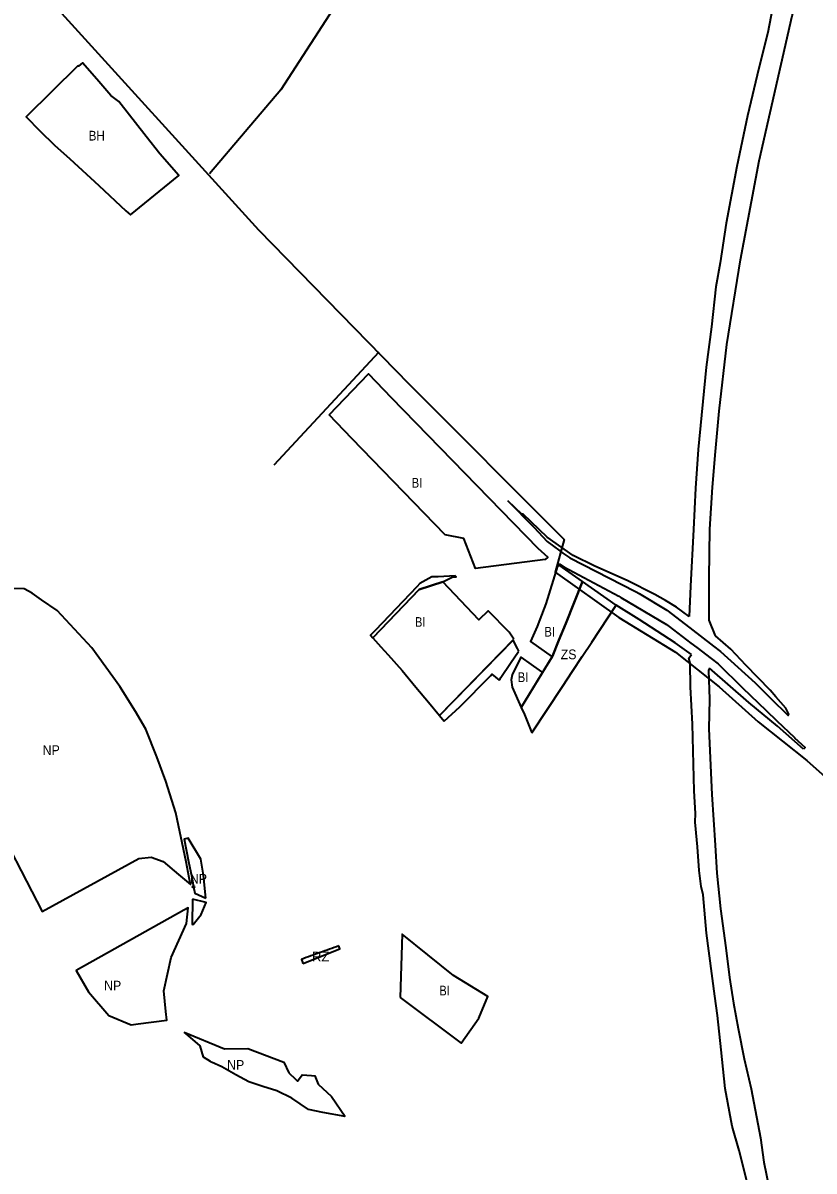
# Model space of a CAD drawing. Extents: x -650276 to -642489, y -1074311 to -1066658.
# Drawn here: x -646196 to -645218, y -1073124 to -1071706 of the extents above; entities that cross this region are included whole.
import ezdxf

# ---------------------------------------------------------------- set-up
doc = ezdxf.new("R2010")
doc.units = 0
doc.header["$LTSCALE"] = 4.8
doc.header["$PDMODE"] = 32
doc.header["$PDSIZE"] = 2.4
for name, color, linetype, lineweight in [('1', 7, 'Continuous', 35), ('15', 7, 'Continuous', 35), ('2', 7, 'Continuous', 35), ('24', 7, 'Continuous', 35), ('41', 7, 'Continuous', 35), ('48', 7, 'Continuous', 35), ('54', 7, 'Continuous', 35), ('6', 7, 'Continuous', 35)]:
    doc.layers.add(name, color=color, linetype=linetype, lineweight=lineweight)
doc.layers.add('62', color=7, linetype='Continuous')

msp = doc.modelspace()

# ---------------------------------------------------------------- linework, layer by layer
at = {"layer": '1'}
msp.add_lwpolyline([(-646102.04, -1071906.4), (-646068.317, -1071937.555), (-646062.91, -1071942.55), (-646002.93, -1071893.984), (-646026.64, -1071867.44), (-646043.49, -1071845.87), (-646077.32, -1071802.59), (-646087, -1071795), (-646104.5, -1071774.86), (-646122.16, -1071754.78), (-646127.12, -1071759.15), (-646127.84, -1071758.53), (-646191.57, -1071821.44), (-646174.69, -1071838.69), (-646156.59, -1071856.53), (-646137.74, -1071873.31)], close=True, dxfattribs=at)
at = {"layer": '15'}
for points in [[(-645661.3, -1072388.74), (-645682.59, -1072389.76), (-645690.37, -1072390.13), (-645705, -1072398.19), (-645708.94, -1072402.11)], [(-645676.53, -1072396.16), (-645676.53, -1072396.16), (-645665.32, -1072390.32), (-645660.16, -1072389.95), (-645661.3, -1072388.74)], [(-645708.94, -1072402.11), (-645760.02, -1072455.94), (-645765.95, -1072462.03), (-645763.06, -1072465.26)], [(-645763.06, -1072465.26), (-645706.039, -1072405.769), (-645676.53, -1072396.16)], [(-645582.84, -1072481.71), (-645584.46, -1072478.58), (-645589.862, -1072468.109), (-645680.87, -1072561.42), (-645675.13, -1072568.36)], [(-645607.07, -1072517.61), (-645605.95, -1072515.95), (-645604.82, -1072514.3), (-645592.9, -1072496.52), (-645583.13, -1072482.13), (-645582.84, -1072481.71)], [(-645675.13, -1072568.36), (-645655.65, -1072550.62), (-645617.87, -1072512.12), (-645615.95, -1072510.16), (-645607.07, -1072517.61)]]:
    msp.add_lwpolyline(points, dxfattribs=at)
at = {"layer": '2'}
for points in [[(-645817.219, -1072189.975), (-645768.649, -1072139.283), (-645740.45, -1072168.23), (-645559.34, -1072354.42), (-645546.82, -1072365.72), (-645550.41, -1072368.47), (-645636.37, -1072379.57), (-645650.78, -1072342.73), (-645674, -1072338), (-645789.298, -1072218.833)], [(-645503.98, -1072395.64), (-645532.75, -1072375.41), (-645535.05, -1072376.72), (-645549.6, -1072423.39), (-645551.54, -1072428.66), (-645559.92, -1072451.41), (-645568.38, -1072469.68), (-645541.56, -1072488.74), (-645553.35, -1072508.1), (-645554.477, -1072507.299), (-645579.92, -1072489.22), (-645581.13, -1072491), (-645591.06, -1072511.06), (-645592.08, -1072517.43), (-645591.03, -1072526.14), (-645579.76, -1072551.45), (-645541.09, -1072487.98), (-645533.15, -1072468.21), (-645524.87, -1072447.61)], [(-645588.78, -1072467), (-645594.83, -1072458.48), (-645620.56, -1072432), (-645632.1, -1072442.93), (-645676.53, -1072396.16), (-645706.039, -1072405.769), (-645763.06, -1072465.26), (-645753.128, -1072476.383), (-645744.38, -1072486.18), (-645726.95, -1072505.7), (-645709.92, -1072526.3), (-645694.51, -1072544.93), (-645680.87, -1072561.42)], [(-645729.36, -1072909.65), (-645654.16, -1072966.3), (-645632.23, -1072935.28), (-645620.92, -1072908.65), (-645663.52, -1072882.58), (-645726.9, -1072831.5)]]:
    msp.add_lwpolyline(points, close=True, dxfattribs=at)
at = {"layer": '24'}
for points in [[(-645339.904, -1072462.677), (-645347.551, -1072443.527), (-645347.677, -1072391.355), (-645346.62, -1072330.914), (-645343.458, -1072278.998), (-645339.908, -1072235.158), (-645335.367, -1072185.207), (-645325.498, -1072102.789), (-645309.01, -1071998.147), (-645285.617, -1071875.733), (-645244.798, -1071696.585), (-645235.793, -1071663.703), (-645230.436, -1071634.261), (-645227.905, -1071625.277), (-645222.48, -1071606.08)], [(-645339.904, -1072462.677), (-645347.551, -1072443.527), (-645347.677, -1072391.355), (-645346.62, -1072330.914), (-645343.458, -1072278.998), (-645339.908, -1072235.158), (-645335.367, -1072185.207), (-645325.498, -1072102.789), (-645309.01, -1071998.147), (-645285.617, -1071875.733), (-645244.798, -1071696.585), (-645235.793, -1071663.703), (-645230.436, -1071634.261), (-645227.905, -1071625.277), (-645222.48, -1071606.08)], [(-645255.662, -1071626.67), (-645261.094, -1071645.025), (-645264.841, -1071657.687), (-645269.077, -1071687.396), (-645274.868, -1071717.176), (-645286.175, -1071761.228), (-645300.076, -1071820.179), (-645313.153, -1071883.081), (-645326.343, -1071952.807)], [(-645255.662, -1071626.67), (-645261.094, -1071645.025), (-645264.841, -1071657.687), (-645269.077, -1071687.396), (-645274.868, -1071717.176), (-645286.175, -1071761.228), (-645300.076, -1071820.179), (-645313.153, -1071883.081)], [(-645313.153, -1071883.081), (-645326.343, -1071952.807), (-645334.118, -1072001.954), (-645339.455, -1072031.565), (-645344.819, -1072081.225), (-645351.358, -1072130.815), (-645361.317, -1072232.824), (-645364.435, -1072280.268), (-645366.951, -1072331.609), (-645370.624, -1072401.447), (-645372.228, -1072438.764)], [(-645326.343, -1071952.807), (-645334.118, -1072001.954), (-645339.455, -1072031.565), (-645344.819, -1072081.225), (-645351.358, -1072130.815), (-645361.317, -1072232.824), (-645364.435, -1072280.268), (-645366.951, -1072331.609), (-645370.624, -1072401.447), (-645372.228, -1072438.764)], [(-645372.228, -1072438.764), (-645387.894, -1072427.453), (-645401.441, -1072419.033), (-645414.631, -1072411.611), (-645448.831, -1072394.325), (-645488.64, -1072376.782), (-645515.437, -1072363.447), (-645547.593, -1072340.827), (-645577.33, -1072312.704), (-645579.217, -1072312.425), (-645596.405, -1072296.114)], [(-645596.405, -1072296.114), (-645564.4, -1072328.61), (-645547.72, -1072346.19), (-645532.07, -1072358.01), (-645531.65, -1072358.29), (-645528.27, -1072360.53), (-645519.57, -1072366.3), (-645438.64, -1072408.1)], [(-645372.228, -1072438.764), (-645387.894, -1072427.453), (-645401.441, -1072419.033), (-645414.631, -1072411.611), (-645448.831, -1072394.325), (-645488.64, -1072376.782), (-645515.437, -1072363.447), (-645547.593, -1072340.827), (-645577.33, -1072312.704), (-645579.217, -1072312.425), (-645596.405, -1072296.114)], [(-645596.405, -1072296.114), (-645564.4, -1072328.61), (-645547.72, -1072346.19), (-645532.07, -1072358.01), (-645531.65, -1072358.29), (-645528.27, -1072360.53), (-645519.57, -1072366.3), (-645438.64, -1072408.1)], [(-645462.646, -1072425.015), (-645503.98, -1072395.64), (-645532.75, -1072375.41), (-645534.3, -1072374.33), (-645533.08, -1072373.71)], [(-645533.08, -1072373.71), (-645527.33, -1072377.73), (-645459.31, -1072413.95), (-645456.52, -1072415.6), (-645400.12, -1072449.03), (-645396.94, -1072451.44), (-645370.226, -1072471.736)], [(-645438.64, -1072408.1), (-645437.6, -1072408.64), (-645434.19, -1072410.67), (-645399.77, -1072431.12), (-645371.356, -1072453.119), (-645342.284, -1072475.625)], [(-645438.64, -1072408.1), (-645437.6, -1072408.64), (-645434.19, -1072410.67), (-645399.77, -1072431.12), (-645371.356, -1072453.119), (-645342.284, -1072475.625), (-645333.62, -1072482.33), (-645290.76, -1072520.92)], [(-645369.364, -1072485.931), (-645389.731, -1072471.612), (-645404.64, -1072461.72), (-645433.91, -1072442.56), (-645462.646, -1072425.015)], [(-645370.226, -1072471.736), (-645362.81, -1072477.37), (-645345.079, -1072490.836)], [(-645290.76, -1072520.92), (-645271.74, -1072539.96), (-645249.9, -1072561.25), (-645248.967, -1072559.511), (-645252.768, -1072552.178), (-645265.009, -1072538.358), (-645272.276, -1072530.154), (-645302.303, -1072499.014), (-645320.805, -1072479.495), (-645339.904, -1072462.677)], [(-645290.76, -1072520.92), (-645271.74, -1072539.96), (-645249.9, -1072561.25), (-645248.967, -1072559.511), (-645252.768, -1072552.178), (-645265.009, -1072538.358), (-645272.276, -1072530.154), (-645302.303, -1072499.014), (-645320.805, -1072479.495), (-645339.904, -1072462.677)], [(-645364.524, -1072682.575), (-645366.022, -1072654.462), (-645368.173, -1072571.881), (-645370.755, -1072525.734), (-645370.928, -1072496.619), (-645372.72, -1072490.314), (-645369.364, -1072485.931)], [(-645342.284, -1072475.625), (-645333.62, -1072482.33), (-645290.76, -1072520.92)], [(-645347.292, -1072502.877), (-645348.253, -1072505.583), (-645347.214, -1072540.97), (-645347.795, -1072577.893), (-645344.152, -1072658.857), (-645339.96, -1072721.587), (-645338.023, -1072755.969), (-645333.718, -1072799.987)], [(-645230.845, -1072602.888), (-645263.217, -1072574.314), (-645298.498, -1072545.352), (-645347.292, -1072502.877)], [(-645345.079, -1072490.836), (-645336.33, -1072497.48), (-645306.46, -1072527.08), (-645276.93, -1072555.11), (-645263.7, -1072567.8), (-645242, -1072588.6), (-645241.87, -1072588.722), (-645228.96, -1072600.865), (-645230.845, -1072602.888)], [(-645357.272, -1072772.771), (-645359.76, -1072752.865), (-645361.874, -1072723.527), (-645362.708, -1072714.781), (-645364.786, -1072692.977), (-645364.524, -1072682.575)], [(-645271.518, -1073261.16), (-645272.747, -1073256.762), (-645275.269, -1073240.71), (-645276.125, -1073226.571), (-645288.647, -1073184.518), (-645297.395, -1073151.294), (-645310.558, -1073098.946), (-645319.052, -1073068.6), (-645327.554, -1073022.214), (-645332.517, -1072974.538), (-645337.34, -1072932.073), (-645340.345, -1072908.029), (-645350.822, -1072830.388), (-645354.019, -1072792.454), (-645355.121, -1072782.993), (-645357.272, -1072772.771)], [(-645333.718, -1072799.987), (-645327.091, -1072848.387), (-645322.284, -1072885.085), (-645317.65, -1072916.642)], [(-645317.65, -1072916.642), (-645311.772, -1072947.945), (-645304.24, -1072985.372), (-645295.788, -1073022.556)], [(-645295.788, -1073022.556), (-645284.269, -1073083.286), (-645279.878, -1073113.356), (-645262.388, -1073199.409), (-645257.842, -1073221.36), (-645247.051, -1073248.736), (-645239.9, -1073270.025), (-645226.847, -1073278.345), (-645227.199, -1073283.366), (-645227.744, -1073292.736)]]:
    msp.add_lwpolyline(points, dxfattribs=at)
at = {"layer": '41'}
msp.add_line((-645566.54, -1072582.88), (-645528.81, -1072525.54), dxfattribs=at)
msp.add_lwpolyline([(-645528.81, -1072525.54), (-645516.37, -1072506.64), (-645504.48, -1072488.58), (-645492.61, -1072470.54), (-645462.65, -1072425.01), (-645503.98, -1072395.64), (-645524.87, -1072447.61), (-645533.15, -1072468.21), (-645541.09, -1072487.98), (-645553.35, -1072508.1), (-645579.76, -1072551.45), (-645575.9, -1072560.13), (-645566.54, -1072582.88)], dxfattribs=at)
at = {"layer": '48'}
for points in [[(-646236.97, -1072678.31), (-646171.72, -1072803.51), (-646052.58, -1072737.82), (-646037.23, -1072736.38), (-646022.4, -1072741.58), (-646003.22, -1072757.85), (-645988.43, -1072769.93), (-645990.04, -1072761.78), (-645993.89, -1072742.23), (-646006.66, -1072681.4), (-646019.16, -1072642.35), (-646030.17, -1072612.31), (-646043.87, -1072578.12), (-646056.42, -1072556.49), (-646075.82, -1072525.54), (-646110.61, -1072477.49), (-646153.49, -1072431.54), (-646172.81, -1072418.2), (-646184.449, -1072410.256), (-646194.19, -1072404.62), (-646254.75, -1072404.25)], [(-645969.46, -1072787.03), (-645972.31, -1072758.48), (-645975.86, -1072738.61), (-645991.31, -1072712.86), (-645996.31, -1072714.11), (-645990.95, -1072741.65), (-645987.1, -1072761.2), (-645984.79, -1072772.91)], [(-645984.79, -1072772.91), (-645983.22, -1072780.88), (-645969.46, -1072787.03)], [(-645986.24, -1072788.33), (-645986.71, -1072819.26), (-645986.71, -1072819.26)], [(-645975.3, -1072807.37), (-645969.01, -1072792.28), (-645986.24, -1072788.33)], [(-645986.71, -1072819.26), (-645986.71, -1072819.26), (-645985.19, -1072819.72), (-645975.3, -1072807.37)], [(-645972.6, -1072983.41), (-645976.48, -1072969.55), (-645988.49, -1072959.28), (-645996.2, -1072952.69)], [(-645996.2, -1072952.69), (-645946.4, -1072973.05), (-645917.53, -1072972.93), (-645873.3, -1072989.79), (-645866.93, -1073002.72)], [(-645863.39, -1073034.25), (-645882.07, -1073025.22), (-645899.35, -1073019.65), (-645916.47, -1073014.03), (-645932.44, -1073005.5), (-645949.85, -1072995.57), (-645962.81, -1072989.45), (-645963.77, -1072989), (-645972.6, -1072983.41)], [(-645866.93, -1073002.72), (-645858.82, -1073010.74), (-645856.46, -1073013.07), (-645850.37, -1073005.42), (-645838.89, -1073006.18)], [(-645838.89, -1073006.18), (-645834.9, -1073006.45), (-645830.6, -1073016.92), (-645814.27, -1073032.11), (-645797.32, -1073056.62)], [(-645797.32, -1073056.62), (-645824.93, -1073051.83), (-645842.53, -1073048.19), (-645863.39, -1073034.25)]]:
    msp.add_lwpolyline(points, dxfattribs=at)
msp.add_lwpolyline([(-645993.47, -1072818.44), (-645991.37, -1072798.84), (-645996.8, -1072801.88), (-646129.91, -1072876.24), (-646114.5, -1072902.8), (-646089.39, -1072931.92), (-646062.04, -1072943.58), (-646053.287, -1072942.399), (-646017.65, -1072937.59), (-646019.21, -1072926.91), (-646021.64, -1072901.6), (-646012.37, -1072860.3)], close=True, dxfattribs=at)
msp.add_point((-645984.79, -1072772.91), dxfattribs=at)
at = {"layer": '54'}
msp.add_line((-645885.363, -1072251.506), (-645755.385, -1072111.972), dxfattribs=at)
for points in [[(-645648.577, -1071395.44), (-645803.784, -1071674.386), (-645877, -1071788), (-645965, -1071892)], [(-646336.784, -1071524.232), (-646218.737, -1071612.767), (-646164.374, -1071674.897), (-645904.456, -1071961.331), (-645718.199, -1072151.712), (-645526.944, -1072343.922), (-645538, -1072384), (-645459, -1072440), (-645389, -1072483), (-645335, -1072526), (-645287, -1072569), (-645227, -1072617), (-645139.573, -1072694.628), (-645084.365, -1072788.086)]]:
    msp.add_lwpolyline(points, dxfattribs=at)
at = {"layer": '6'}
for points in [[(-645834.208, -1072856.314), (-645837.027, -1072857.313), (-645839.908, -1072858.343), (-645842.74, -1072859.344), (-645845.619, -1072860.364), (-645848.628, -1072861.433), (-645851.48, -1072862.586), (-645850.187, -1072866.251), (-645850.17, -1072866.3), (-645849.705, -1072867.618), (-645849.703, -1072867.622)], [(-645849.703, -1072867.622), (-645848.52, -1072867.16), (-645803.84, -1072849.72), (-645805.159, -1072845.994)], [(-645805.159, -1072845.994), (-645808.177, -1072847.063), (-645811.148, -1072848.124), (-645813.978, -1072849.124), (-645816.948, -1072850.184), (-645819.779, -1072851.184), (-645822.726, -1072852.233), (-645825.527, -1072853.233), (-645828.409, -1072854.254), (-645834.208, -1072856.314)]]:
    msp.add_lwpolyline(points, dxfattribs=at)

# ---------------------------------------------------------------- texts
at = {"layer": '62'}
for s, width, p in [('BH', 0.9, (-646114.48, -1071850.818)), ('BI', 0.85, (-645715.06, -1072279.771)), ('BI', 0.85, (-645711.104, -1072451.727)), ('BI', 0.85, (-645551.06, -1072463.771)), ('ZS', 0.95, (-645531.06, -1072491.771)), ('BI', 0.85, (-645584, -1072520)), ('NP', 0.95, (-646171.335, -1072610.048)), ('NP', 0.95, (-645989.335, -1072769.048)), ('NP', 0.95, (-646095.335, -1072901.048)), ('BI', 0.85, (-645681, -1072907.167)), ('NP', 0.95, (-645943.335, -1072999.048))]:
    msp.add_text(s, height=12, dxfattribs=dict(at, width=width)).set_placement(p)
msp.add_text('RZ', height=12, dxfattribs=at).set_placement((-645838.415, -1072865.224))

doc.saveas('drawing.dxf')
